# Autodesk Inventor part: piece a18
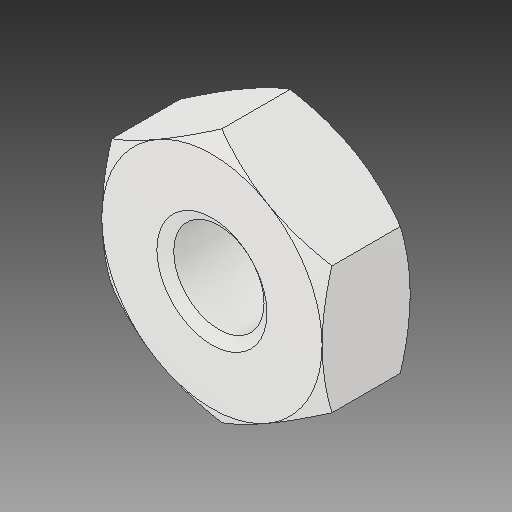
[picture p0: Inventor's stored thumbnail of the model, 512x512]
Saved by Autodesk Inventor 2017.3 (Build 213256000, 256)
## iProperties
Created: 1999-08
Part Number: piece a18
Material: solidworks materials|Alliage 7079|22
Document SubType Name: Modeling
Designer: ficho
Appearance: 255,255,255
Author: ficho
Sending System: SolidWorks 2009
Last Author: christophe
Last Saved: 2011-01-17
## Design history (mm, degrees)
feature "EndChamfer"
node "Solide1"
